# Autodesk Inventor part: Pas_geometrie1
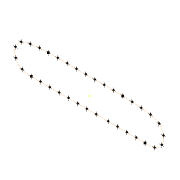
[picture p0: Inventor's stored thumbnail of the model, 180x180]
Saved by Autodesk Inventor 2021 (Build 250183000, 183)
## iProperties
Created: 2024-12
Part Number: Pas_geometrie1
Material: Všeobecné
Document SubType Name: Modeling
Designer: tatulinek
Density: 1 g/cm^3
Appearance: Výchozí
Author: tatulinek
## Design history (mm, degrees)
sketch "Náčrt1"
  geometry: 71 further points
  constraints: 33 coincident, 39 other
